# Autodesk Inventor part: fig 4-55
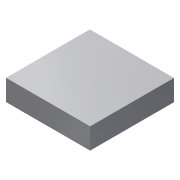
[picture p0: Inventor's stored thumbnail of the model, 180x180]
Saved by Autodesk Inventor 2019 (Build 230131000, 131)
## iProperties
Created: 2010-02
Part Number: fig 4-55
Document SubType Name: Modeling
Designer: CADSoft
Density: 1 g/cm^3
Material: Generic
Appearance: Default
Author: CADSoft
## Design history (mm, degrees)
sketch "Sketch1"
  geometry: L1 (-20.026, 19.961)-(0, 19.961); L2 (0, 19.961)-(0, 0); L3 (0, 0)-(-20.026, 0); L4 (-20.026, 0)-(-20.026, 19.961)
  constraints: 8 end point
extrude "Extrusion1" new body sketch "Sketch1" distance "d0" = 5; taper "d1" = 0 deg
body "Solid1"
